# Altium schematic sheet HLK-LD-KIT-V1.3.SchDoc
size A4
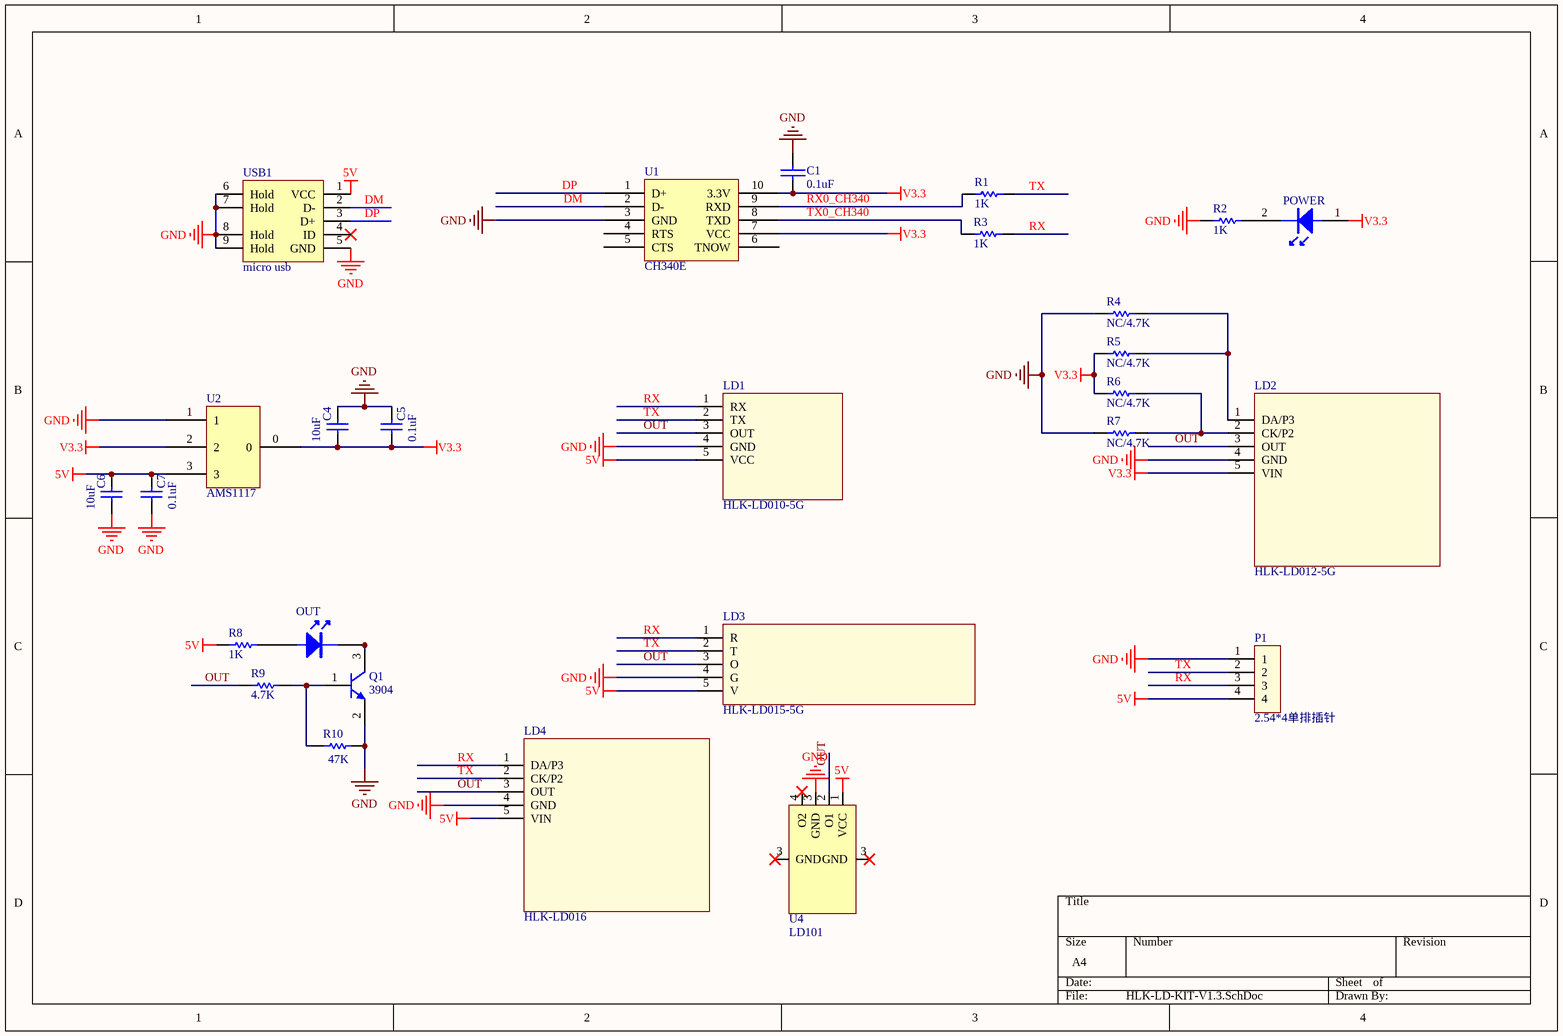
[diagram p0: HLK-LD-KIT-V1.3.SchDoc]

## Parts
C1  0.1uF  [0603]
C4  10uF  [0603]
C5  0.1uF  [0603]
C6  10uF  [0603]
C7  0.1uF  [0603]
LD1  HLK-LD010-5G  [HLK-LD010-5G]
LD2  HLK-LD012-5G  [HLK-LD012-5G]
LD3  HLK-LD015-5G  [HLK-LD015-5G]
LD4  HLK-LD016  [HLK-LD012-5G]
OUT  (no value)  [0603LED]
P1  2.54*4单排插针  [SIP_4P_2.54]
POWER  LED  [0603LED]  (value not drawn)
Q1  3904  [SOT-23]
R1  1K  [0603]
R2  1K  [0603]
R3  1K  [0603]
R4  NC/4.7K  [0603]
R5  NC/4.7K  [0603]
R6  NC/4.7K  [0603]
R7  NC/4.7K  [0603]
R8  1K  [0603]
R9  4.7K  [0603]
R10  47K  [0603]
U1  CH340E  [MSOP-10]
U2  AMS1117  [1117]
U4  LD101  [LD101插座]
USB1  micro usb  [USB-MICRO_D]

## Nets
5V: C6.1 C7.1 LD1.5(VCC) LD3.5(V) LD4.5(VIN) P1.4 R8.1 U2.3 U4.1(VCC) USB1.1(VCC)
GND: C1.1 C4.1 C5.1 C6.2 C7.2 LD1.4(GND) LD2.4(GND) LD3.4(G) LD4.4(GND) P1.1 Q1.2(E) R2.2 R4.2 R7.2 R10.1 U1.3(GND) U2.1 U4.3(GND) USB1.5(GND) USB1.6(Hold) USB1.7(Hold) USB1.8(Hold) USB1.9(Hold)
V3.3: C1.2 C4.2 C5.2 LD2.5(VIN) POWER.1 R5.2 R6.2 U1.7(VCC) U1.10(3.3V) U2.0 U2.2
DM: U1.2(D-) USB1.2(D-)
DP: U1.1(D+) USB1.3(D+)
OUT: LD1.3(OUT) LD2.3(OUT) LD3.3(O) LD4.3(OUT) R9.2 U4.2(O1)
RX: LD1.1(RX) LD3.1(R) LD4.1(DA/P3) P1.3 R3.1
RX0_CH340: R1.2 U1.9(RXD)
TX: LD1.2(TX) LD3.2(T) LD4.2(CK/P2) P1.2 R1.1
TX0_CH340: R3.2 U1.8(TXD)
NetLD2_1: LD2.1(DA/P3) R4.1 R5.1
NetLD2_2: LD2.2(CK/P2) R6.1 R7.1
NetOUT_1: OUT.1 R8.2
NetOUT_2: OUT.2 Q1.3(C)
NetPOWER_2: POWER.2 R2.1
NetQ1_1: Q1.1(B) R9.1 R10.2

Not connected (* = marked no-connect by the designer): U1 4(RTS) 5(CTS) 6(TNOW); U4 4(O2)*; USB1 4(ID)*

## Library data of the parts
C1 = CAP: Capacitor
C4-C7 = Cap: Capacitor; Value: 100pF
LD4 = HLK-LD012-5G
OUT = LED
P1 = 2.54*2插针
Q1 = A09T: NPN General Purpose Amplifier
R1-R10 = Res1: Resistor
U2 = Component_1
USB1 = USB-D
